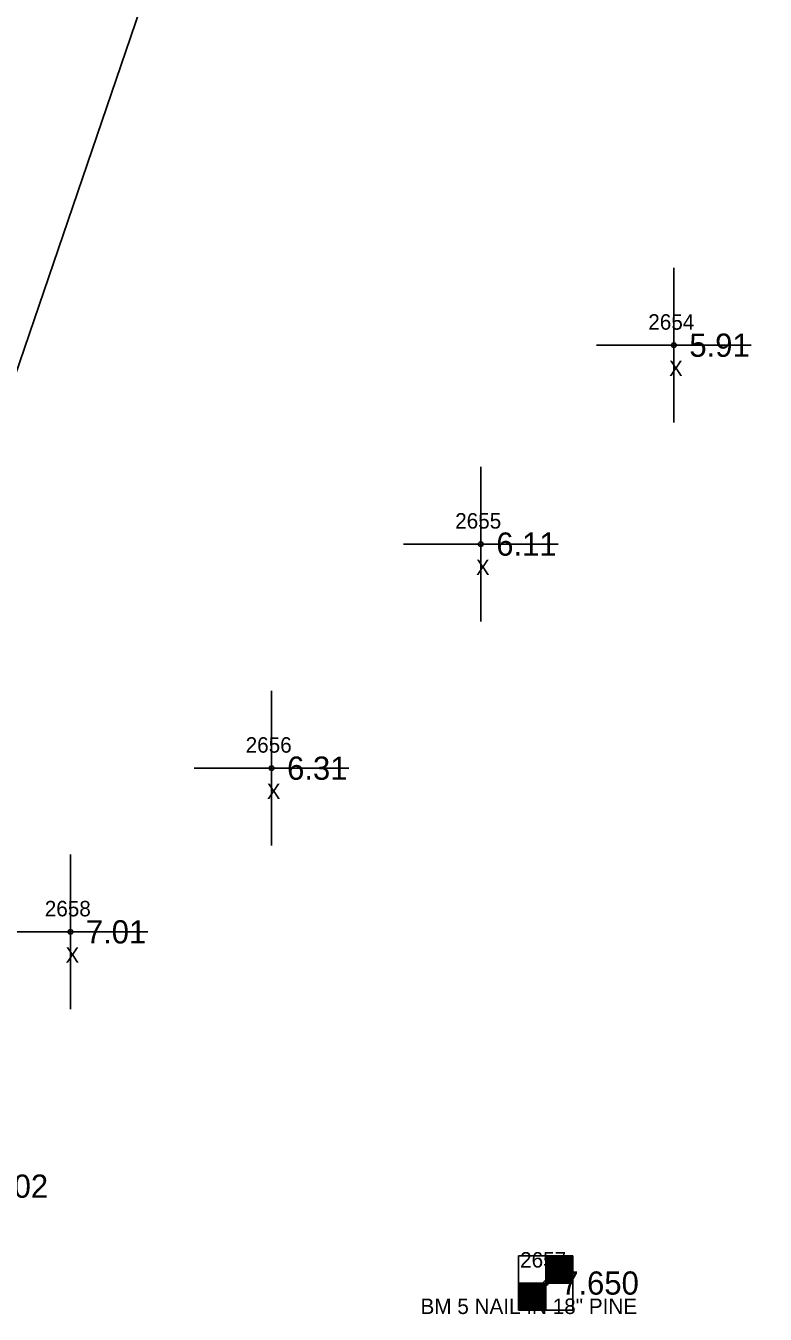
# Model space of a CAD drawing. Extents: x 2042211 to 2045853, y 303080 to 309569.
# Drawn here: x 2044737.2 to 2044785, y 304425.3 to 304508.5 of the extents above; entities that cross this region are included whole.
import ezdxf

# ---------------------------------------------------------------- set-up
doc = ezdxf.new("R2010")
doc.units = 0
for name, color, linetype in [('BR_500YR_SCOUR', 7, 'Continuous'), ('RD_EX_H2O', 7, 'Continuous'), ('RD_EX_Misc', 7, 'Continuous'), ('RD_EX_Misc_txCode', 7, 'Continuous'), ('RD_EX_TX_Misc_ELEV', 7, 'Continuous'), ('RD_EX_TX_VEG_ELEV', 7, 'Continuous'), ('RD_HC_Survey_ELEV', 7, 'Continuous'), ('RD_HC_Survey_txCode', 7, 'Continuous'), ('RD_SMD_Locator', 7, 'Continuous')]:
    doc.layers.add(name, color=color, linetype=linetype)

msp = doc.modelspace()

# ---------------------------------------------------------------- linework, layer by layer
at = {"layer": 'BR_500YR_SCOUR'}
for p, q in [((2044770.813, 304429.041), (2044770.813, 304425.541)), ((2044770.83, 304429.041), (2044770.83, 304427.291)), ((2044770.855, 304429.041), (2044770.855, 304427.291)), ((2044770.88, 304429.041), (2044770.88, 304427.291)), ((2044770.905, 304429.041), (2044770.905, 304427.291)), ((2044770.929, 304429.041), (2044770.929, 304427.291)), ((2044770.954, 304429.041), (2044770.954, 304427.291)), ((2044770.979, 304429.041), (2044770.979, 304427.291)), ((2044771.004, 304429.041), (2044771.004, 304427.291)), ((2044771.028, 304429.041), (2044771.028, 304427.291)), ((2044771.053, 304429.041), (2044771.053, 304427.291)), ((2044771.078, 304429.041), (2044771.078, 304427.291)), ((2044771.103, 304429.041), (2044771.103, 304427.291)), ((2044771.127, 304429.041), (2044771.127, 304427.291)), ((2044771.152, 304429.041), (2044771.152, 304427.291)), ((2044771.177, 304429.041), (2044771.177, 304427.291)), ((2044771.202, 304429.041), (2044771.202, 304427.291)), ((2044771.226, 304429.041), (2044771.226, 304427.291)), ((2044771.251, 304429.041), (2044771.251, 304427.291)), ((2044771.276, 304429.041), (2044771.276, 304427.291)), ((2044771.301, 304429.041), (2044771.301, 304427.291)), ((2044771.325, 304429.041), (2044771.325, 304427.291)), ((2044771.35, 304429.041), (2044771.35, 304427.291)), ((2044771.375, 304429.041), (2044771.375, 304427.291)), ((2044771.4, 304429.041), (2044771.4, 304427.291)), ((2044771.424, 304429.041), (2044771.424, 304427.291)), ((2044771.449, 304429.041), (2044771.449, 304427.291)), ((2044771.474, 304429.041), (2044771.474, 304427.291)), ((2044771.499, 304429.041), (2044771.499, 304427.291)), ((2044771.523, 304429.041), (2044771.523, 304427.291)), ((2044771.548, 304429.041), (2044771.548, 304427.291)), ((2044771.573, 304429.041), (2044771.573, 304427.291)), ((2044771.597, 304429.041), (2044771.597, 304427.291)), ((2044771.622, 304429.041), (2044771.622, 304427.291)), ((2044771.647, 304429.041), (2044771.647, 304427.291)), ((2044771.672, 304429.041), (2044771.672, 304427.291)), ((2044771.696, 304429.041), (2044771.696, 304427.291)), ((2044771.721, 304429.041), (2044771.721, 304427.291)), ((2044771.746, 304429.041), (2044771.746, 304427.291)), ((2044771.771, 304429.041), (2044771.771, 304427.291)), ((2044771.795, 304429.041), (2044771.795, 304427.291)), ((2044771.82, 304429.041), (2044771.82, 304427.291)), ((2044771.845, 304429.041), (2044771.845, 304427.291)), ((2044771.87, 304429.041), (2044771.87, 304427.291)), ((2044771.894, 304429.041), (2044771.894, 304427.291)), ((2044771.919, 304429.041), (2044771.919, 304427.291)), ((2044771.944, 304429.041), (2044771.944, 304427.291)), ((2044771.969, 304429.041), (2044771.969, 304427.291)), ((2044771.993, 304429.041), (2044771.993, 304427.291)), ((2044772.018, 304429.041), (2044772.018, 304427.291)), ((2044772.043, 304429.041), (2044772.043, 304427.291)), ((2044772.068, 304429.041), (2044772.068, 304427.291)), ((2044772.092, 304429.041), (2044772.092, 304427.291)), ((2044772.117, 304429.041), (2044772.117, 304427.291)), ((2044772.142, 304429.041), (2044772.142, 304427.291)), ((2044772.167, 304429.041), (2044772.167, 304427.291)), ((2044772.191, 304429.041), (2044772.191, 304427.291)), ((2044772.216, 304429.041), (2044772.216, 304427.291)), ((2044772.241, 304429.041), (2044772.241, 304427.291)), ((2044772.266, 304429.041), (2044772.266, 304427.291)), ((2044772.29, 304429.041), (2044772.29, 304427.291)), ((2044772.315, 304429.041), (2044772.315, 304427.291)), ((2044772.34, 304429.041), (2044772.34, 304427.291)), ((2044772.365, 304429.041), (2044772.365, 304427.291)), ((2044772.389, 304429.041), (2044772.389, 304427.291)), ((2044772.414, 304429.041), (2044772.414, 304427.291)), ((2044772.439, 304429.041), (2044772.439, 304427.291)), ((2044772.464, 304429.041), (2044772.464, 304427.291)), ((2044772.488, 304429.041), (2044772.488, 304427.291)), ((2044772.513, 304429.041), (2044772.513, 304427.291)), ((2044772.538, 304429.041), (2044772.538, 304427.291)), ((2044772.563, 304427.291), (2044769.063, 304427.291)), ((2044769.063, 304427.291), (2044769.063, 304425.541)), ((2044769.087, 304427.291), (2044769.087, 304425.541)), ((2044769.112, 304427.291), (2044769.112, 304425.541)), ((2044769.137, 304427.291), (2044769.137, 304425.541)), ((2044769.162, 304427.291), (2044769.162, 304425.541)), ((2044769.186, 304427.291), (2044769.186, 304425.541)), ((2044769.211, 304427.291), (2044769.211, 304425.541)), ((2044769.236, 304427.291), (2044769.236, 304425.541)), ((2044769.261, 304427.291), (2044769.261, 304425.541)), ((2044769.285, 304427.291), (2044769.285, 304425.541)), ((2044769.31, 304427.291), (2044769.31, 304425.541)), ((2044769.335, 304427.291), (2044769.335, 304425.541)), ((2044769.36, 304427.291), (2044769.36, 304425.541)), ((2044769.384, 304427.291), (2044769.384, 304425.541)), ((2044769.409, 304427.291), (2044769.409, 304425.541)), ((2044769.434, 304427.291), (2044769.434, 304425.541)), ((2044769.459, 304427.291), (2044769.459, 304425.541)), ((2044769.483, 304427.291), (2044769.483, 304425.541)), ((2044769.508, 304427.291), (2044769.508, 304425.541)), ((2044769.533, 304427.291), (2044769.533, 304425.541)), ((2044769.558, 304427.291), (2044769.558, 304425.541)), ((2044769.582, 304427.291), (2044769.582, 304425.541)), ((2044769.607, 304427.291), (2044769.607, 304425.541)), ((2044769.632, 304427.291), (2044769.632, 304425.541)), ((2044769.657, 304427.291), (2044769.657, 304425.541)), ((2044769.681, 304427.291), (2044769.681, 304425.541)), ((2044769.706, 304427.291), (2044769.706, 304425.541)), ((2044769.731, 304427.291), (2044769.731, 304425.541)), ((2044769.756, 304427.291), (2044769.756, 304425.541)), ((2044769.78, 304427.291), (2044769.78, 304425.541)), ((2044769.805, 304427.291), (2044769.805, 304425.541)), ((2044769.83, 304427.291), (2044769.83, 304425.541)), ((2044769.855, 304427.291), (2044769.855, 304425.541)), ((2044769.879, 304427.291), (2044769.879, 304425.541)), ((2044769.904, 304427.291), (2044769.904, 304425.541)), ((2044769.929, 304427.291), (2044769.929, 304425.541)), ((2044769.954, 304427.291), (2044769.954, 304425.541)), ((2044769.978, 304427.291), (2044769.978, 304425.541)), ((2044770.003, 304427.291), (2044770.003, 304425.541)), ((2044770.028, 304427.291), (2044770.028, 304425.541)), ((2044770.053, 304427.291), (2044770.053, 304425.541)), ((2044770.077, 304427.291), (2044770.077, 304425.541)), ((2044770.102, 304427.291), (2044770.102, 304425.541)), ((2044770.127, 304427.291), (2044770.127, 304425.541)), ((2044770.152, 304427.291), (2044770.152, 304425.541)), ((2044770.176, 304427.291), (2044770.176, 304425.541)), ((2044770.201, 304427.291), (2044770.201, 304425.541)), ((2044770.226, 304427.291), (2044770.226, 304425.541)), ((2044770.251, 304427.291), (2044770.251, 304425.541)), ((2044770.275, 304427.291), (2044770.275, 304425.541)), ((2044770.3, 304427.291), (2044770.3, 304425.541)), ((2044770.325, 304427.291), (2044770.325, 304425.541)), ((2044770.35, 304427.291), (2044770.35, 304425.541)), ((2044770.374, 304427.291), (2044770.374, 304425.541)), ((2044770.399, 304427.291), (2044770.399, 304425.541)), ((2044770.424, 304427.291), (2044770.424, 304425.541)), ((2044770.449, 304427.291), (2044770.449, 304425.541)), ((2044770.473, 304427.291), (2044770.473, 304425.541)), ((2044770.498, 304427.291), (2044770.498, 304425.541)), ((2044770.523, 304427.291), (2044770.523, 304425.541)), ((2044770.548, 304427.291), (2044770.548, 304425.541)), ((2044770.572, 304427.291), (2044770.572, 304425.541)), ((2044770.597, 304427.291), (2044770.597, 304425.541)), ((2044770.622, 304427.291), (2044770.622, 304425.541)), ((2044770.647, 304427.291), (2044770.647, 304425.541)), ((2044770.671, 304427.291), (2044770.671, 304425.541)), ((2044770.696, 304427.291), (2044770.696, 304425.541)), ((2044770.721, 304427.291), (2044770.721, 304425.541)), ((2044770.746, 304427.291), (2044770.746, 304425.541)), ((2044770.77, 304427.291), (2044770.77, 304425.541)), ((2044770.795, 304427.291), (2044770.795, 304425.541))]:
    msp.add_line(p, q, dxfattribs=at)
msp.add_lwpolyline([(2044772.563, 304429.041), (2044769.063, 304429.041), (2044769.063, 304425.541), (2044772.563, 304425.541)], close=True, dxfattribs=at)
msp.add_circle((2044770.813, 304427.291), 0.15, dxfattribs=at)
at = {"layer": 'RD_EX_H2O'}
msp.add_lwpolyline([(2044719.894, 304440.119), (2044724.283, 304439.56), (2044726.758, 304444.252), (2044726.489, 304449.957), (2044727.038, 304454.868), (2044730.565, 304468.482), (2044746.811, 304516.02), (2044772.025, 304609.791), (2044801.757, 304708.942), (2044831.053, 304807.037), (2044857.931, 304905.053)], dxfattribs=at)
at = {"layer": 'RD_EX_Misc'}
for p, q in [((2044779.096, 304482.868), (2044779.096, 304492.868)), ((2044774.096, 304487.868), (2044784.096, 304487.868)), ((2044766.617, 304470.021), (2044766.617, 304480.021)), ((2044761.617, 304475.021), (2044771.617, 304475.021)), ((2044753.099, 304455.548), (2044753.099, 304465.548)), ((2044748.099, 304460.548), (2044758.099, 304460.548)), ((2044740.093, 304444.976), (2044740.093, 304454.976)), ((2044735.093, 304449.976), (2044745.093, 304449.976))]:
    msp.add_line(p, q, dxfattribs=at)
at = {"layer": 'RD_SMD_Locator'}
for centre in [(2044779.096, 304487.868), (2044766.617, 304475.021), (2044753.099, 304460.548), (2044740.093, 304449.976)]:
    msp.add_circle(centre, 0.15, dxfattribs=at)

# ---------------------------------------------------------------- texts
at = {"layer": 'RD_EX_Misc_txCode'}
for s, p in [('2654', (2044777.442, 304488.868)), ('X', (2044778.781, 304485.868)), ('2655', (2044764.964, 304476.021)), ('X', (2044766.302, 304473.021)), ('2656', (2044751.422, 304461.548)), ('X', (2044752.784, 304458.548)), ('2658', (2044738.439, 304450.976)), ('X', (2044739.778, 304447.976))]:
    msp.add_text(s, height=1, dxfattribs=at).set_placement(p)
at = {"layer": 'RD_EX_TX_Misc_ELEV'}
for s, p in [('5.91', (2044780.096, 304487.118)), ('6.11', (2044767.617, 304474.271)), ('6.31', (2044754.099, 304459.798)), ('7.01', (2044741.093, 304449.226))]:
    msp.add_text(s, height=1.5, dxfattribs=at).set_placement(p)
at = {"layer": 'RD_EX_TX_VEG_ELEV'}
msp.add_text('8.02', height=1.5, dxfattribs=at).set_placement((2044734.752, 304432.798))
at = {"layer": 'RD_HC_Survey_ELEV'}
msp.add_text('7.650', height=1.5, dxfattribs=at).set_placement((2044771.813, 304426.541))
at = {"layer": 'RD_HC_Survey_txCode'}
for s, p in [('2657', (2044769.159, 304428.291)), ('BM 5 NAIL IN 18" PINE', (2044762.722, 304425.291))]:
    msp.add_text(s, height=1, dxfattribs=at).set_placement(p)

doc.saveas('drawing.dxf')
